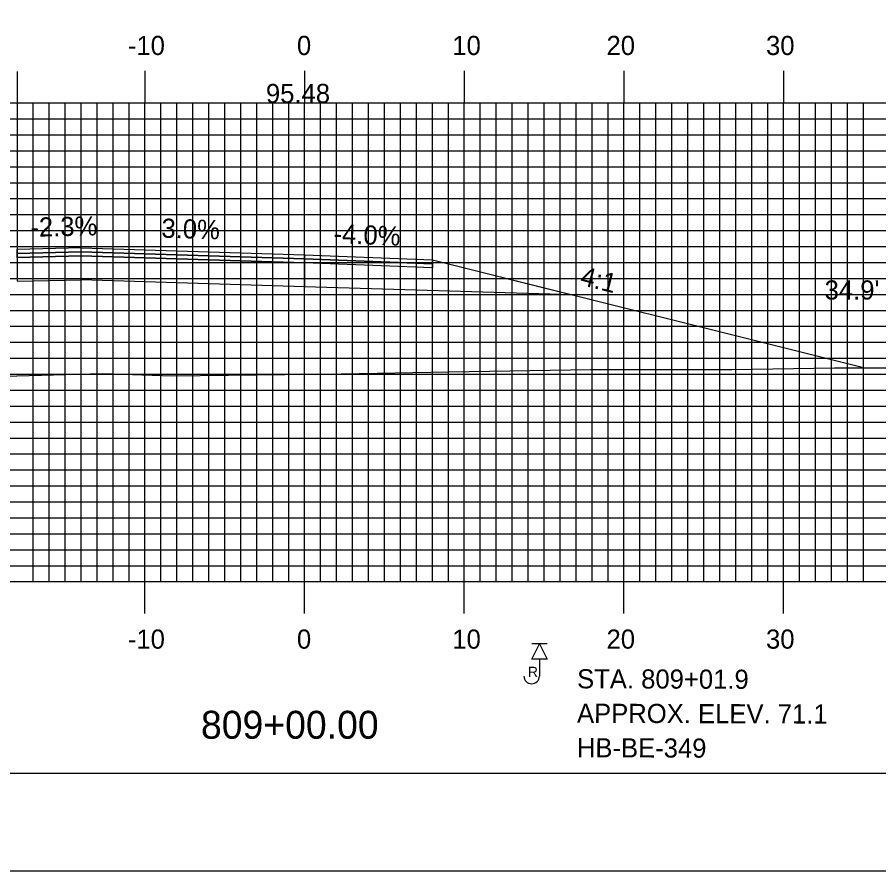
# Model space of a CAD drawing. Extents: x 1666 to 2009, y -1658 to -1438.
# Drawn here: x 1813.7 to 1867.6, y -1657.7 to -1604.2 of the extents above; entities that cross this region are included whole.
import ezdxf

# ---------------------------------------------------------------- set-up
doc = ezdxf.new("R2010")
doc.units = 0
for name, color, linetype in [('ANNOTATION', 7, 'Continuous'), ('BORDER', 7, 'Continuous'), ('BORING - REFUSAL', 7, 'Continuous'), ('D_Roadway_Centerline_Text', 7, 'Continuous'), ('D_Roadway_Edge_Shoulder', 7, 'Continuous'), ('D_Roadway_Edge_TW', 7, 'Continuous'), ('D_Roadway_Pavement', 7, 'Continuous'), ('D_Roadway_SlopeLines', 7, 'Continuous'), ('D_Roadway_SubGrade', 7, 'Continuous'), ('D_Text_Standard', 7, 'Continuous'), ('H_V ANNOTATION', 7, 'Continuous'), ('MAJOR', 7, 'Continuous'), ('MINOR', 7, 'Continuous'), ('PLOT BOUNDARY', 7, 'Continuous'), ('S_Roadway_Centerline', 7, 'Continuous')]:
    doc.layers.add(name, color=color, linetype=linetype)

msp = doc.modelspace()

# ---------------------------------------------------------------- linework, layer by layer
at = {"layer": 'BORDER'}
msp.add_lwpolyline([(1682.074, -1651.604), (2002.074, -1651.604), (2002.074, -1441.604), (1682.074, -1441.604)], close=True, dxfattribs=at)
at = {"layer": 'BORING - REFUSAL'}
for p, q in [((1846.853, -1643.503), (1845.894, -1643.503)), ((1846.374, -1644.463), (1846.374, -1645.522))]:
    msp.add_line(p, q, dxfattribs=at)
msp.add_lwpolyline([(1846.374, -1643.503), (1846.853, -1644.463), (1845.894, -1644.463)], close=True, dxfattribs=at)
msp.add_arc((1845.889, -1645.522), 0.485, 180, 0, dxfattribs=at)
at = {"layer": 'D_Roadway_Edge_Shoulder'}
for points in [[(1817.674, -1618.694), (1813.674, -1618.787), (1813.674, -1619.037), (1817.674, -1618.944)], [(1831.674, -1619.12), (1839.674, -1619.44), (1839.674, -1619.69), (1831.674, -1619.37)], [(1831.674, -1619.37), (1839.674, -1619.69), (1839.674, -1619.94), (1831.674, -1619.62)]]:
    msp.add_lwpolyline(points, close=True, dxfattribs=at)
at = {"layer": 'D_Roadway_Edge_TW'}
msp.add_lwpolyline([(1817.674, -1618.694), (1831.674, -1619.12), (1831.674, -1619.37), (1817.674, -1618.944)], close=True, dxfattribs=at)
at = {"layer": 'D_Roadway_Pavement'}
for points in [[(1817.674, -1618.944), (1813.674, -1619.037), (1813.674, -1619.287), (1817.674, -1619.194)], [(1817.674, -1618.944), (1831.674, -1619.37), (1831.674, -1619.62), (1817.674, -1619.194)]]:
    msp.add_lwpolyline(points, close=True, dxfattribs=at)
msp.add_lwpolyline([(1831.674, -1619.37), (1831.674, -1619.62)], dxfattribs=at)
msp.add_lwpolyline([(1831.674, -1619.37), (1831.674, -1619.62)], dxfattribs=at)
at = {"layer": 'D_Roadway_SlopeLines'}
msp.add_lwpolyline([(1839.674, -1619.44), (1866.6, -1626.172)], dxfattribs=at)
at = {"layer": 'D_Roadway_SubGrade'}
msp.add_line((1813.674, -1607.634), (1813.674, -1620.774), dxfattribs=at)
for points in [[(1817.674, -1619.194), (1813.674, -1619.287), (1813.674, -1619.037), (1813.674, -1618.787), (1813.674, -1620.774), (1817.674, -1620.694)], [(1817.674, -1619.194), (1831.674, -1619.62), (1831.674, -1621.12), (1817.674, -1620.694)], [(1831.674, -1619.62), (1831.674, -1619.37), (1839.674, -1619.69), (1839.674, -1619.44), (1848.432, -1621.63), (1831.674, -1621.12)]]:
    msp.add_lwpolyline(points, close=True, dxfattribs=at)
at = {"layer": 'MAJOR'}
for p, q in [((1821.674, -1607.6), (1821.674, -1609.604)), ((1831.674, -1607.6), (1831.674, -1609.604)), ((1841.674, -1607.6), (1841.674, -1609.604)), ((1851.674, -1607.6), (1851.674, -1609.604)), ((1861.674, -1607.6), (1861.674, -1609.604)), ((1691.674, -1609.604), (1971.674, -1609.604)), ((1691.674, -1609.604), (1971.674, -1609.604)), ((1821.674, -1639.604), (1821.674, -1609.604)), ((1831.674, -1639.604), (1831.674, -1609.604)), ((1841.674, -1639.604), (1841.674, -1609.604)), ((1851.674, -1639.604), (1851.674, -1609.604)), ((1861.674, -1639.604), (1861.674, -1609.604)), ((1691.674, -1614.604), (1971.674, -1614.604)), ((1691.674, -1619.604), (1971.674, -1619.604)), ((1691.674, -1624.604), (1971.674, -1624.604)), ((1691.674, -1629.604), (1971.674, -1629.604)), ((1691.674, -1634.604), (1971.674, -1634.604)), ((1691.674, -1639.604), (1971.674, -1639.604)), ((1691.674, -1639.604), (1971.674, -1639.604)), ((1821.674, -1641.608), (1821.674, -1639.604)), ((1831.674, -1641.608), (1831.674, -1639.604)), ((1841.674, -1641.608), (1841.674, -1639.604)), ((1851.674, -1641.608), (1851.674, -1639.604)), ((1861.674, -1641.608), (1861.674, -1639.604))]:
    msp.add_line(p, q, dxfattribs=at)
at = {"layer": 'MINOR'}
for p, q in [((1814.674, -1639.604), (1814.674, -1609.604)), ((1815.674, -1639.604), (1815.674, -1609.604)), ((1816.674, -1639.604), (1816.674, -1609.604)), ((1817.674, -1639.604), (1817.674, -1609.604)), ((1818.674, -1639.604), (1818.674, -1609.604)), ((1819.674, -1639.604), (1819.674, -1609.604)), ((1820.674, -1639.604), (1820.674, -1609.604)), ((1822.674, -1639.604), (1822.674, -1609.604)), ((1823.674, -1639.604), (1823.674, -1609.604)), ((1824.674, -1639.604), (1824.674, -1609.604)), ((1825.674, -1639.604), (1825.674, -1609.604)), ((1826.674, -1639.604), (1826.674, -1609.604)), ((1827.674, -1639.604), (1827.674, -1609.604)), ((1828.674, -1639.604), (1828.674, -1609.604)), ((1829.674, -1639.604), (1829.674, -1609.604)), ((1830.674, -1639.604), (1830.674, -1609.604)), ((1832.674, -1639.604), (1832.674, -1609.604)), ((1833.674, -1639.604), (1833.674, -1609.604)), ((1834.674, -1639.604), (1834.674, -1609.604)), ((1835.674, -1639.604), (1835.674, -1609.604)), ((1836.674, -1639.604), (1836.674, -1609.604)), ((1837.674, -1639.604), (1837.674, -1609.604)), ((1838.674, -1639.604), (1838.674, -1609.604)), ((1839.674, -1639.604), (1839.674, -1609.604)), ((1840.674, -1639.604), (1840.674, -1609.604)), ((1842.674, -1639.604), (1842.674, -1609.604)), ((1843.674, -1639.604), (1843.674, -1609.604)), ((1844.674, -1639.604), (1844.674, -1609.604)), ((1845.674, -1639.604), (1845.674, -1609.604)), ((1846.674, -1639.604), (1846.674, -1609.604)), ((1847.674, -1639.604), (1847.674, -1609.604)), ((1848.674, -1639.604), (1848.674, -1609.604)), ((1849.674, -1639.604), (1849.674, -1609.604)), ((1850.674, -1639.604), (1850.674, -1609.604)), ((1852.674, -1639.604), (1852.674, -1609.604)), ((1853.674, -1639.604), (1853.674, -1609.604)), ((1854.674, -1639.604), (1854.674, -1609.604)), ((1855.674, -1639.604), (1855.674, -1609.604)), ((1856.674, -1639.604), (1856.674, -1609.604)), ((1857.674, -1639.604), (1857.674, -1609.604)), ((1858.674, -1639.604), (1858.674, -1609.604)), ((1859.674, -1639.604), (1859.674, -1609.604)), ((1860.674, -1639.604), (1860.674, -1609.604)), ((1862.674, -1639.604), (1862.674, -1609.604)), ((1863.674, -1639.604), (1863.674, -1609.604)), ((1864.674, -1639.604), (1864.674, -1609.604)), ((1865.674, -1639.604), (1865.674, -1609.604)), ((1866.674, -1639.604), (1866.674, -1609.604)), ((1691.674, -1610.604), (1971.674, -1610.604)), ((1691.674, -1611.604), (1971.674, -1611.604)), ((1691.674, -1612.604), (1971.674, -1612.604)), ((1691.674, -1613.604), (1971.674, -1613.604)), ((1691.674, -1615.604), (1971.674, -1615.604)), ((1691.674, -1616.604), (1971.674, -1616.604)), ((1691.674, -1617.604), (1971.674, -1617.604)), ((1691.674, -1618.604), (1971.674, -1618.604)), ((1691.674, -1620.604), (1971.674, -1620.604)), ((1691.674, -1621.604), (1971.674, -1621.604)), ((1691.674, -1622.604), (1971.674, -1622.604)), ((1691.674, -1623.604), (1971.674, -1623.604)), ((1691.674, -1625.604), (1971.674, -1625.604)), ((1691.674, -1626.604), (1971.674, -1626.604)), ((1691.674, -1627.604), (1971.674, -1627.604)), ((1691.674, -1628.604), (1971.674, -1628.604)), ((1691.674, -1630.604), (1971.674, -1630.604)), ((1691.674, -1631.604), (1971.674, -1631.604)), ((1691.674, -1632.604), (1971.674, -1632.604)), ((1691.674, -1633.604), (1971.674, -1633.604)), ((1691.674, -1635.604), (1971.674, -1635.604)), ((1691.674, -1636.604), (1971.674, -1636.604)), ((1691.674, -1637.604), (1971.674, -1637.604)), ((1691.674, -1638.604), (1971.674, -1638.604))]:
    msp.add_line(p, q, dxfattribs=at)
at = {"layer": 'PLOT BOUNDARY'}
msp.add_lwpolyline([(1665.887, -1657.723), (2005.887, -1657.723), (2005.887, -1437.723), (1665.887, -1437.723)], close=True, dxfattribs=at)
at = {"layer": 'S_Roadway_Centerline'}
msp.add_lwpolyline([(1691.674, -1630.506), (1698.876, -1630.25), (1711.689, -1629.994), (1715.82, -1629.915), (1721.305, -1629.719), (1734.01, -1629.339), (1742.956, -1628.959), (1752.121, -1628.587), (1764.61, -1628.321), (1770.004, -1628.13), (1774.157, -1627.999), (1787.265, -1627.509), (1804.928, -1626.941), (1805.349, -1626.927), (1805.982, -1626.922), (1819.016, -1626.554), (1823.37, -1626.71), (1833.959, -1626.589), (1840.695, -1626.449), (1849.589, -1626.314), (1856.031, -1626.306), (1858.435, -1626.306), (1864.854, -1626.2), (1877.053, -1626.205)], dxfattribs=at)

# ---------------------------------------------------------------- texts
at = {"layer": 'ANNOTATION'}
for s, rotation, p in [('-2.3%', 1.3274, (1814.512, -1617.997)), ('3.0%', 358.2581, (1822.691, -1618.046)), ('-4.0%', 357.7094, (1833.465, -1618.39)), ('4:1', 345.9638, (1848.868, -1620.994))]:
    msp.add_text(s, height=1.2, rotation=rotation, dxfattribs=at).set_placement(p)
at = {"layer": 'BORING - REFUSAL'}
msp.add_text('R', height=0.64, dxfattribs=at).set_placement((1845.665, -1645.578))
for s, p in [('STA. 809+01.9', (1848.736, -1646.289)), ('APPROX. ELEV. 71.1', (1848.729, -1648.449)), ('HB-BE-349', (1848.722, -1650.609))]:
    msp.add_text(s, height=1.2, rotation=359.8142, dxfattribs=at).set_placement(p)
at = {"layer": 'D_Roadway_Centerline_Text'}
msp.add_text('95.48', height=1.2, dxfattribs=at).set_placement((1829.25, -1609.613))
at = {"layer": 'D_Text_Standard'}
msp.add_text("34.9'", height=1.2, dxfattribs=at).set_placement((1864.24, -1621.926))
at = {"layer": 'H_V ANNOTATION'}
for s, height, p in [('-10', 1.2, (1820.603, -1606.604)), ('0', 1.2, (1831.192, -1606.604)), ('10', 1.2, (1840.924, -1606.604)), ('20', 1.2, (1850.582, -1606.604)), ('30', 1.2, (1860.571, -1606.604)), ('-10', 1.2, (1820.603, -1643.804)), ('0', 1.2, (1831.192, -1643.804)), ('10', 1.2, (1840.924, -1643.804)), ('20', 1.2, (1850.582, -1643.804)), ('30', 1.2, (1860.571, -1643.804)), ('809+00.00', 1.75, (1825.181, -1649.448))]:
    msp.add_text(s, height=height, dxfattribs=at).set_placement(p)

doc.saveas('drawing.dxf')
